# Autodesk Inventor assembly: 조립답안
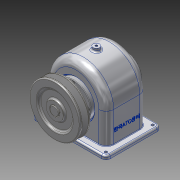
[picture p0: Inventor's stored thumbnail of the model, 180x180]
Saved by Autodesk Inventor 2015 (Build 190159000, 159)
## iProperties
Created: 2016-01
Part Number: 조립답안
Document SubType Name: Assembly
Designer: 601-23
Author: 601-23
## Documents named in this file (15)
- C:\Users\601-23\Desktop\460106V1044\조립답안.iam
- C:\Users\601-23\Desktop\460106V1044\본체.ipt
- C:\Users\601-23\Desktop\460106V1044\축.ipt
- C:\Users\601-23\Desktop\460106V1044\베어링 6203.ipt
- C:\Users\601-23\Desktop\460106V1044\키 - 5 x 5 x 18.ipt
- C:\Users\601-23\Desktop\460106V1044\키 - 6 x 6 x 22.ipt
- C:\Users\601-23\Desktop\460106V1044\부시1.ipt
- C:\Users\601-23\Desktop\460106V1044\스퍼기어.ipt
- C:\Users\601-23\Desktop\460106V1044\앞커버.ipt
- C:\Users\601-23\Desktop\460106V1044\뒤커버.ipt
- C:\Users\601-23\Desktop\460106V1044\부시2.ipt
- C:\Users\601-23\Desktop\460106V1044\오일씰 28 40 8.ipt
- C:\Users\601-23\Desktop\460106V1044\V-벨트풀리.ipt
- C:\Users\601-23\Desktop\460106V1044\볼트 M3 x 8.ipt
- C:\Users\601-23\Desktop\460106V1044\볼트 M3 x 10.ipt
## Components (9 placed, 3 different names)
1. V-벨트풀리:1
2. ISO 4762 M3 x 8:1
3. ISO 4762 M3 x 8:2
4. ISO 4762 M3 x 8:3
5. ISO 4762 M3 x 8:4
6. ISO 4762 M3 x 10:1
7. ISO 4762 M3 x 10:2
8. ISO 4762 M3 x 10:3
9. ISO 4762 M3 x 10:4
